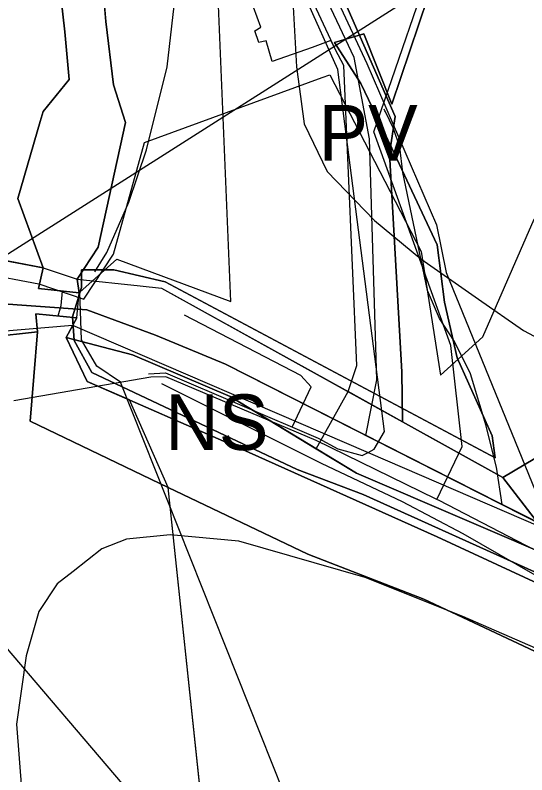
# Model space of a CAD drawing. Extents: x -758499 to -754160, y -1175205 to -1172032.
# Drawn here: x -756217.8 to -756125.8, y -1174335.6 to -1174199 of the extents above; entities that cross this region are included whole.
import ezdxf

# ---------------------------------------------------------------- set-up
doc = ezdxf.new("R2010")
doc.units = 0
for name, color, linetype in [('A011_UrbHod_p', 7, 'Continuous'), ('A016_UzArchN_p', 7, 'Continuous'), ('A022_vkpr_p', 7, 'Continuous'), ('A041_BPEJ_p', 7, 'Continuous'), ('A051_QAZ_p', 7, 'Continuous'), ('A068_Vodovod_l', 7, 'Continuous'), ('A070_Kanal_l', 7, 'Continuous'), ('A075_Plyn_l', 7, 'Continuous'), ('A106_CykloT_l', 7, 'Continuous'), ('A106_TuristT_l', 7, 'Continuous'), ('D cyklocesty NÁVRH', 7, 'Continuous'), ('HRANICE zastavěného území', 7, 'Continuous'), ('HRANICE zastavěného území - podbarvení', 7, 'Continuous'), ('indexy RZV_TYP_1', 7, 'Continuous'), ('PLOCHY NS smíšené nezastavěného území', 7, 'Continuous'), ('PLOCHY PV prostranství veřejné', 7, 'Continuous'), ('PLOCHY PZ prostr veřejné-zeleň veřejná', 7, 'Continuous'), ('PLOCHY SO smíšené obytné', 7, 'Continuous'), ('PLOCHY VV vodní a vodohospodářské', 7, 'Continuous'), ('vrstevnice', 7, 'Continuous'), ('ÚSES LBC jako součást RBK', 7, 'Continuous'), ('ÚSES NBK funkční', 7, 'Continuous')]:
    doc.layers.add(name, color=color, linetype=linetype)

msp = doc.modelspace()

# ---------------------------------------------------------------- linework, layer by layer
at = {"layer": 'A011_UrbHod_p'}
msp.add_lwpolyline([(-756273.23, -1174274.4), (-756251.11, -1174265.71), (-756254.17, -1174258.81), (-756256.09, -1174254.46), (-756248.06, -1174251.43), (-756234.08, -1174247.57), (-756223.73, -1174245.39), (-756213.55, -1174247.3), (-756205.43, -1174250.06), (-756200.11, -1174241.96), (-756194.56, -1174221.89), (-756162.56, -1174210.19), (-756161.22, -1174209.7), (-756153.15, -1174225.26), (-756144.74, -1174241.49), (-756141.27, -1174263.74), (-756133.65, -1174256.85), (-756124.46, -1174235.67), (-756101.79, -1174229.35), (-756097.1, -1174218.12), (-756091.08, -1174200.15), (-756064.31, -1174207.17), (-756013.75, -1174223.19), (-755992.59, -1174161.72)], dxfattribs=at)
at = {"layer": 'A016_UzArchN_p'}
for p, q in [((-756115.25, -1174175.88), (-756258.5, -1174267)), ((-756258.5, -1174267), (-756014.06, -1174553.25))]:
    msp.add_line(p, q, dxfattribs=at)
at = {"layer": 'A022_vkpr_p'}
for p, q in [((-756178.68, -1174393.04), (-756190.27, -1174283.91)), ((-756190.27, -1174283.91), (-756165.18, -1174295.93)), ((-756165.18, -1174295.93), (-756144.28, -1174304.01)), ((-756144.28, -1174304.01), (-756123.38, -1174313.87))]:
    msp.add_line(p, q, dxfattribs=at)
at = {"layer": 'A041_BPEJ_p'}
for p, q in [((-756135.66, -1174172.55), (-756150.06, -1174214.97)), ((-756150.06, -1174214.97), (-756135.66, -1174172.55)), ((-756155.07, -1174202.3), (-756160.35, -1174203.89)), ((-756160.35, -1174203.89), (-756155.07, -1174202.3)), ((-756150.06, -1174214.97), (-756155.07, -1174202.3)), ((-756155.07, -1174202.3), (-756150.06, -1174214.97)), ((-756160.35, -1174203.89), (-756155.6, -1174211.28)), ((-756155.6, -1174211.28), (-756160.35, -1174203.89)), ((-756155.6, -1174211.28), (-756150.06, -1174222.89)), ((-756150.06, -1174222.89), (-756155.6, -1174211.28)), ((-756150.06, -1174222.89), (-756141.87, -1174240.31)), ((-756141.87, -1174240.31), (-756150.06, -1174222.89)), ((-756141.87, -1174240.31), (-756140.55, -1174250.6)), ((-756140.55, -1174250.6), (-756141.87, -1174240.31)), ((-756200.07, -1174244.8), (-756205.88, -1174244.8)), ((-756205.88, -1174244.8), (-756205.88, -1174247.96)), ((-756205.88, -1174247.96), (-756205.88, -1174244.8)), ((-756205.88, -1174244.8), (-756200.07, -1174244.8)), ((-756190.83, -1174246.91), (-756200.07, -1174244.8)), ((-756200.07, -1174244.8), (-756190.83, -1174246.91)), ((-756131.45, -1174278.58), (-756190.83, -1174246.91)), ((-756190.83, -1174246.91), (-756131.45, -1174278.58)), ((-756205.88, -1174247.96), (-756207.46, -1174253.24)), ((-756207.46, -1174253.24), (-756205.88, -1174247.96)), ((-756140.55, -1174250.6), (-756138.31, -1174260.63)), ((-756138.31, -1174260.63), (-756140.55, -1174250.6)), ((-756207.46, -1174253.24), (-756207.2, -1174257.47)), ((-756207.2, -1174257.47), (-756207.46, -1174253.24)), ((-756207.2, -1174257.47), (-756204.03, -1174263.27)), ((-756204.03, -1174263.27), (-756207.2, -1174257.47)), ((-756138.31, -1174260.63), (-756131.98, -1174274.62)), ((-756131.98, -1174274.62), (-756138.31, -1174260.63)), ((-756204.03, -1174263.27), (-756167.08, -1174280.69)), ((-756167.08, -1174280.69), (-756204.03, -1174263.27)), ((-756131.98, -1174274.62), (-756131.45, -1174278.58)), ((-756131.45, -1174278.58), (-756131.98, -1174274.62)), ((-756167.08, -1174280.69), (-756155.2, -1174285.18)), ((-756155.2, -1174285.18), (-756167.08, -1174280.69)), ((-756155.2, -1174285.18), (-756111.92, -1174304.71)), ((-756111.92, -1174304.71), (-756155.2, -1174285.18))]:
    msp.add_line(p, q, dxfattribs=at)
at = {"layer": 'A051_QAZ_p'}
for p, q in [((-756179.01, -1174250.46), (-756182.79, -1174159.77)), ((-756206.16, -1174248.79), (-756199.51, -1174242.87)), ((-756199.51, -1174242.87), (-756179.01, -1174250.46)), ((-756205.87, -1174257.36), (-756206.16, -1174248.79)), ((-756203.12, -1174262.12), (-756205.87, -1174257.36)), ((-756198.86, -1174264.97), (-756203.12, -1174262.12)), ((-756153.06, -1174380.18), (-756198.86, -1174264.97))]:
    msp.add_line(p, q, dxfattribs=at)
at = {"layer": 'A068_Vodovod_l'}
for p, q in [((-756137.36, -1174276.58), (-756139.44, -1174258.38)), ((-756193.37, -1174264.1), (-756218.03, -1174268.35)), ((-756190.67, -1174264.04), (-756193.37, -1174264.1)), ((-756163.64, -1174275.48), (-756190.67, -1174264.04)), ((-756142.21, -1174285.95), (-756163.64, -1174275.48)), ((-756141.96, -1174286.07), (-756137.36, -1174276.58)), ((-756137.36, -1174276.58), (-756137.36, -1174276.58)), ((-756141.96, -1174286.07), (-756142.21, -1174285.95)), ((-756141.55, -1174286.27), (-756141.96, -1174286.07)), ((-756125.95, -1174294.36), (-756141.55, -1174286.27)), ((-756110.23, -1174302.42), (-756125.95, -1174294.36))]:
    msp.add_line(p, q, dxfattribs=at)
msp.add_lwpolyline([(-756139.44, -1174258.38), (-756153.26, -1174219.96), (-756141, -1174184.15), (-756144.04, -1174183.03)], dxfattribs=at)
at = {"layer": 'A070_Kanal_l'}
for p, q in [((-756185.83, -1174140.48), (-756154.55, -1174207.64)), ((-756159.78, -1174208.74), (-756181.48, -1174160.35)), ((-756154.55, -1174207.64), (-756142.01, -1174236.68)), ((-756151.37, -1174273.86), (-756159.78, -1174208.74)), ((-756142.01, -1174236.68), (-756140.29, -1174245.27)), ((-756140.29, -1174245.27), (-756122.25, -1174289.44)), ((-756231.7, -1174256.79), (-756207.48, -1174254.72)), ((-756207.48, -1174254.72), (-756154.32, -1174277.62)), ((-756193.8, -1174263.51), (-756190.73, -1174263.32)), ((-756190.73, -1174263.32), (-756163.29, -1174275.04)), ((-756163.29, -1174275.04), (-756159.78, -1174276.96)), ((-756153.23, -1174277.05), (-756151.37, -1174273.86)), ((-756159.78, -1174276.96), (-756155.35, -1174278.15)), ((-756155.35, -1174278.15), (-756154.32, -1174277.62)), ((-756154.32, -1174277.62), (-756153.23, -1174277.05)), ((-756154.32, -1174277.62), (-756123.28, -1174290.98))]:
    msp.add_line(p, q, dxfattribs=at)
at = {"layer": 'A075_Plyn_l'}
for p, q in [((-756151.29, -1174216.15), (-756151.42, -1174215.9)), ((-756151.19, -1174216.35), (-756151.29, -1174216.15)), ((-756149.74, -1174219.36), (-756151.19, -1174216.35)), ((-756148.6, -1174222.69), (-756149.74, -1174219.36)), ((-756148.05, -1174227.3), (-756148.6, -1174222.69)), ((-756144.79, -1174243.04), (-756148.05, -1174227.3)), ((-756143.61, -1174248.52), (-756144.79, -1174243.04)), ((-756141.45, -1174253.56), (-756143.61, -1174248.52)), ((-756138.74, -1174257.7), (-756141.45, -1174253.56)), ((-756135.91, -1174263.5), (-756138.74, -1174257.7)), ((-756133.09, -1174272.82), (-756135.91, -1174263.5)), ((-756131.67, -1174278.44), (-756133.09, -1174272.82)), ((-756131.2, -1174280.27), (-756131.67, -1174278.44)), ((-756130.17, -1174286.97), (-756131.2, -1174280.27)), ((-756106.83, -1174298.8), (-756130.17, -1174286.97))]:
    msp.add_line(p, q, dxfattribs=at)
at = {"layer": 'A106_CykloT_l'}
msp.add_line((-756107.33, -1174298.61), (-756179.99, -1174261.74), dxfattribs=at)
msp.add_lwpolyline([(-756179.99, -1174261.74), (-756192.58, -1174256.56), (-756204.92, -1174251.95), (-756222.5, -1174250.7), (-756239.57, -1174253.38)], dxfattribs=at)
at = {"layer": 'A106_TuristT_l'}
msp.add_lwpolyline([(-756280.72, -1174271.65), (-756256.13, -1174262.02), (-756239.57, -1174253.38), (-756222.5, -1174250.7), (-756204.92, -1174251.95), (-756192.58, -1174256.56), (-756179.99, -1174261.74), (-756107.33, -1174298.61), (-756057.45, -1174324.38), (-756008.08, -1174348.69), (-755979.53, -1174356.92), (-755950.61, -1174360.91), (-755921.19, -1174365.14), (-755890.52, -1174356.42), (-755882.54, -1174346.19), (-755873.57, -1174325.5)], dxfattribs=at)
at = {"layer": 'D cyklocesty NÁVRH'}
msp.add_lwpolyline([(-756154.73, -1174274.55), (-756152.77, -1174264.54), (-756154.08, -1174221.2), (-756156.83, -1174206.56), (-756191.69, -1174132.71), (-756234.52, -1174057.12), (-756239.02, -1174041.46), (-756245.97, -1174018.41), (-756249.6, -1173995.8), (-756304.39, -1173806.64)], dxfattribs=at)
at = {"layer": 'HRANICE zastavěného území'}
msp.add_lwpolyline([(-756121.16, -1174484.1), (-756160.87, -1174439.93), (-756178.68, -1174393.04), (-756183.55, -1174347.23), (-756190.27, -1174283.91), (-756165.18, -1174295.93), (-756144.28, -1174304.01), (-756123.38, -1174313.87), (-756113.04, -1174306.18), (-756117.96, -1174297.85), (-756156.4, -1174281.38), (-756163.67, -1174276.95), (-756157.91, -1174266.69), (-756156.32, -1174261.99), (-756158.7, -1174208.04), (-756160.17, -1174205.21), (-756160.99, -1174203.5), (-756164.38, -1174204.76), (-756171.54, -1174207.3), (-756172.67, -1174203.59), (-756173.94, -1174203.88), (-756174.68, -1174201.8), (-756173.61, -1174201.15), (-756174.91, -1174197.56)], dxfattribs=at)
at = {"layer": 'HRANICE zastavěného území - podbarvení'}
msp.add_lwpolyline([(-756121.16, -1174484.1), (-756160.87, -1174439.93), (-756178.68, -1174393.04), (-756183.55, -1174347.23), (-756190.27, -1174283.91), (-756165.18, -1174295.93), (-756144.28, -1174304.01), (-756123.38, -1174313.87), (-756113.04, -1174306.18), (-756117.96, -1174297.85), (-756156.4, -1174281.38), (-756163.67, -1174276.95), (-756157.91, -1174266.69), (-756156.32, -1174261.99), (-756158.7, -1174208.04), (-756160.17, -1174205.21), (-756160.99, -1174203.5), (-756164.38, -1174204.76), (-756171.54, -1174207.3), (-756172.67, -1174203.59), (-756173.94, -1174203.88), (-756174.68, -1174201.8), (-756173.61, -1174201.15), (-756174.91, -1174197.56)], dxfattribs=at)
at = {"layer": 'PLOCHY NS smíšené nezastavěného území'}
msp.add_lwpolyline([(-756270.79, -1174043.15), (-756264.52, -1174054.74), (-756260.72, -1174070.36), (-756230.35, -1174096.54), (-756206.25, -1174136.36), (-756213.14, -1174141.86), (-756214.02, -1174157.76), (-756211.95, -1174174.95), (-756208.86, -1174201.97), (-756208.07, -1174210.57), (-756212.77, -1174216.28), (-756213.29, -1174218.07), (-756217.29, -1174231.93), (-756212.79, -1174244.39), (-756223.76, -1174242.33), (-756234.79, -1174244.65), (-756248.99, -1174248.57), (-756260.11, -1174252.77), (-756270.28, -1174234.38), (-756281.77, -1174208.37)], dxfattribs=at)
for points in [[(-756168.32, -1174187.67), (-756183.7, -1174154.58), (-756192.29, -1174137.68), (-756196.84, -1174140.13), (-756205.49, -1174146.31), (-756205.53, -1174155.92), (-756204.03, -1174171.48), (-756201.48, -1174200.1), (-756200.09, -1174211.48), (-756197.95, -1174218.25), (-756202.88, -1174240.71), (-756206.66, -1174246.47), (-756195.33, -1174247.66), (-756191.48, -1174248.06), (-756157.91, -1174266.69), (-756156.32, -1174261.99), (-756158.7, -1174208.04), (-756160.17, -1174205.21)], [(-756163.67, -1174276.95), (-756156.4, -1174281.38), (-756117.96, -1174297.85), (-756113.04, -1174306.18), (-756141.86, -1174292.8), (-756177.45, -1174276.86), (-756204.82, -1174264.87), (-756208.63, -1174256.96), (-756196.7, -1174260.04), (-756179.1, -1174267.55)]]:
    msp.add_lwpolyline(points, close=True, dxfattribs=at)
at = {"layer": 'PLOCHY PV prostranství veřejné'}
for points in [[(-756163.98, -1174184.12), (-756149.47, -1174217.22), (-756150.49, -1174223.88), (-756148.26, -1174263.13), (-756148.13, -1174272.12), (-756157.91, -1174266.69), (-756156.32, -1174261.99), (-756158.7, -1174208.04), (-756160.17, -1174205.21), (-756168.32, -1174187.67)], [(-756223.76, -1174242.33), (-756212.79, -1174244.39), (-756213.59, -1174248.15), (-756206.29, -1174248.89), (-756206.66, -1174246.47), (-756195.33, -1174247.66), (-756191.48, -1174248.06), (-756130.06, -1174282.15), (-756117.96, -1174297.85), (-756156.4, -1174281.38), (-756179.1, -1174267.55), (-756196.7, -1174260.04), (-756208.63, -1174256.96), (-756206.73, -1174253.42), (-756214.07, -1174252.68), (-756213.79, -1174255.92), (-756231.23, -1174257.84)], [(-756117.96, -1174297.85), (-756130.06, -1174282.15), (-756124.3, -1174278.74)]]:
    msp.add_lwpolyline(points, dxfattribs=at)
at = {"layer": 'PLOCHY PZ prostr veřejné-zeleň veřejná'}
msp.add_lwpolyline([(-756165.04, -1174469.72), (-756185.2, -1174444), (-756204.68, -1174407.86), (-756217.85, -1174364.29), (-756233.34, -1174320.49), (-756242.77, -1174292.8), (-756253.42, -1174267.91), (-756240.56, -1174260.05), (-756231.23, -1174257.84), (-756213.79, -1174255.92), (-756215.09, -1174272.02), (-756190.27, -1174283.91), (-756165.18, -1174295.93), (-756144.28, -1174304.01), (-756123.38, -1174313.87)], dxfattribs=at)
at = {"layer": 'PLOCHY SO smíšené obytné'}
msp.add_lwpolyline([(-756124.3, -1174278.74), (-756130.06, -1174282.15), (-756148.13, -1174272.12), (-756148.26, -1174263.13), (-756150.49, -1174223.88), (-756149.47, -1174217.22), (-756163.98, -1174184.12)], dxfattribs=at)
at = {"layer": 'PLOCHY VV vodní a vodohospodářské'}
for p, q in [((-756209.5, -1174251.19), (-756209.26, -1174248.59)), ((-756210.09, -1174253.08), (-756209.5, -1174251.19))]:
    msp.add_line(p, q, dxfattribs=at)
msp.add_lwpolyline([(-756204.03, -1174171.48), (-756201.48, -1174200.1), (-756200.09, -1174211.48), (-756197.95, -1174218.25), (-756202.88, -1174240.71), (-756206.66, -1174246.47), (-756206.29, -1174248.89), (-756213.59, -1174248.15), (-756212.79, -1174244.39), (-756217.29, -1174231.93), (-756213.29, -1174218.07), (-756212.77, -1174216.28), (-756208.07, -1174210.57), (-756208.86, -1174201.97), (-756211.95, -1174174.95)], dxfattribs=at)
msp.add_lwpolyline([(-756214.07, -1174252.68), (-756206.73, -1174253.42), (-756208.63, -1174256.96), (-756204.82, -1174264.87), (-756177.45, -1174276.86), (-756141.86, -1174292.8), (-756113.04, -1174306.18), (-756123.38, -1174313.87), (-756144.28, -1174304.01), (-756165.18, -1174295.93), (-756190.27, -1174283.91), (-756215.09, -1174272.02), (-756213.79, -1174255.92)], close=True, dxfattribs=at)
at = {"layer": 'vrstevnice'}
for p, q in [((-756167.86, -1174196.38), (-756167.17, -1174208.24)), ((-756190.43, -1174208.28), (-756189.22, -1174197.32)), ((-756190.43, -1174208.28), (-756189.22, -1174197.32)), ((-756194.15, -1174223.21), (-756190.43, -1174208.28)), ((-756194.15, -1174223.21), (-756190.43, -1174208.28)), ((-756167.17, -1174208.24), (-756165.79, -1174218.52)), ((-756165.79, -1174218.52), (-756161.66, -1174227.12)), ((-756197.36, -1174232.61), (-756194.15, -1174223.21)), ((-756197.36, -1174232.61), (-756194.15, -1174223.21)), ((-756161.66, -1174227.12), (-756153.18, -1174235.89)), ((-756201.32, -1174241.66), (-756197.36, -1174232.61)), ((-756201.32, -1174241.66), (-756197.36, -1174232.61)), ((-756153.18, -1174235.89), (-756144.84, -1174242.8)), ((-756203.46, -1174245.11), (-756201.32, -1174241.66)), ((-756203.46, -1174245.11), (-756201.32, -1174241.66)), ((-756144.84, -1174242.8), (-756134.48, -1174250.05)), ((-756134.48, -1174250.05), (-756126.34, -1174255.67)), ((-756166.43, -1174263.8), (-756187.32, -1174252.92)), ((-756166.43, -1174263.8), (-756187.32, -1174252.92)), ((-756126.34, -1174255.67), (-756115.99, -1174261.27)), ((-756164.57, -1174265.8), (-756166.43, -1174263.8)), ((-756164.57, -1174265.8), (-756166.43, -1174263.8)), ((-756162.72, -1174279.64), (-756191.4, -1174265.27)), ((-756162.72, -1174279.64), (-756191.4, -1174265.27)), ((-756167.97, -1174273.06), (-756164.57, -1174265.8)), ((-756167.97, -1174273.06), (-756164.57, -1174265.8)), ((-756148.13, -1174286.49), (-756162.72, -1174279.64)), ((-756148.13, -1174286.49), (-756162.72, -1174279.64)), ((-756137.23, -1174292.27), (-756148.13, -1174286.49)), ((-756137.23, -1174292.27), (-756148.13, -1174286.49)), ((-756189.9, -1174292.43), (-756197.8, -1174293.24)), ((-756189.9, -1174292.43), (-756197.8, -1174293.24)), ((-756177.57, -1174293.6), (-756189.9, -1174292.43)), ((-756177.57, -1174293.6), (-756189.9, -1174292.43)), ((-756124.23, -1174299.68), (-756137.23, -1174292.27)), ((-756124.23, -1174299.68), (-756137.23, -1174292.27)), ((-756197.8, -1174293.24), (-756202.23, -1174294.94)), ((-756197.8, -1174293.24), (-756202.23, -1174294.94)), ((-756154.81, -1174300.13), (-756177.57, -1174293.6)), ((-756154.81, -1174300.13), (-756177.57, -1174293.6)), ((-756202.23, -1174294.94), (-756207.34, -1174299.03)), ((-756202.23, -1174294.94), (-756207.34, -1174299.03)), ((-756207.34, -1174299.03), (-756210.26, -1174301.26)), ((-756207.34, -1174299.03), (-756210.26, -1174301.26)), ((-756137.28, -1174307.13), (-756154.81, -1174300.13)), ((-756137.28, -1174307.13), (-756154.81, -1174300.13)), ((-756210.26, -1174301.26), (-756213.52, -1174306.26)), ((-756210.26, -1174301.26), (-756213.52, -1174306.26)), ((-756213.52, -1174306.26), (-756215.84, -1174314.19)), ((-756213.52, -1174306.26), (-756215.84, -1174314.19)), ((-756124.2, -1174312.86), (-756137.28, -1174307.13)), ((-756124.2, -1174312.86), (-756137.28, -1174307.13)), ((-756215.84, -1174314.19), (-756217.56, -1174326.52)), ((-756215.84, -1174314.19), (-756217.56, -1174326.52)), ((-756217.56, -1174326.52), (-756215.91, -1174348.04)), ((-756217.56, -1174326.52), (-756215.91, -1174348.04))]:
    msp.add_line(p, q, dxfattribs=at)
at = {"layer": 'ÚSES LBC jako součást RBK'}
for p, q in [((-756201.48, -1174200.1), (-756204.03, -1174171.48)), ((-756202.88, -1174240.71), (-756197.95, -1174218.25)), ((-756206.66, -1174246.47), (-756202.88, -1174240.71)), ((-756223.76, -1174242.33), (-756212.79, -1174244.39)), ((-756212.79, -1174244.39), (-756206.66, -1174246.47))]:
    msp.add_line(p, q, dxfattribs=at)
msp.add_lwpolyline([(-756197.95, -1174218.25), (-756200.09, -1174211.48), (-756201.48, -1174200.1)], dxfattribs=at)
at = {"layer": 'ÚSES NBK funkční'}
for p, q in [((-756206.29, -1174248.89), (-756206.66, -1174246.47)), ((-756206.73, -1174253.42), (-756206.29, -1174248.89)), ((-756208.63, -1174256.96), (-756206.73, -1174253.42)), ((-756204.82, -1174264.87), (-756208.63, -1174256.96)), ((-756197.26, -1174268.18), (-756204.82, -1174264.87)), ((-756190.27, -1174283.91), (-756197.26, -1174268.18)), ((-756178.68, -1174393.04), (-756190.27, -1174283.91))]:
    msp.add_line(p, q, dxfattribs=at)

# ---------------------------------------------------------------- texts
at = {"layer": 'indexy RZV_TYP_1'}
for s, p in [('PV', (-756163.23, -1174225.13)), ('NS', (-756190.82, -1174277.2))]:
    msp.add_text(s, height=10, dxfattribs=at).set_placement(p)

doc.saveas('drawing.dxf')
